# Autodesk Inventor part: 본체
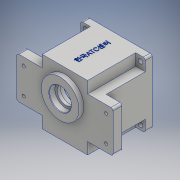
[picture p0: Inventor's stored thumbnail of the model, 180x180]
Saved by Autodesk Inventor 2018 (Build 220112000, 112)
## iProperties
Created: 2020-07
Part Number: 본체
Material: 알루미늄 6061
Document SubType Name: Modeling
Designer: admin
Density: 2.7 g/cm^3
Appearance: 알루미늄 - 평지
Mass: 876.486 g
Surface Area: 793.573 cm^2
Volume: 324.624 cm^3
Author: admin
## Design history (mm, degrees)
sketch "스케치1"
  geometry: L1 (65.8, 0)-(-65.8, 0) reference; L2 (0, -65.8)-(0, 65.8) reference; L3 (47, -47)-(-47, -47); L4 (-47, -47)-(-47, 47); L5 (-47, 47)-(47, 47); L6 (47, 47)-(47, -47); L7 (47, -47)-(-47, 47); L8 (-47, -47)-(47, 47); 1 further point
  constraints: 12 end point, 2 midpoint, 2 parallel, 1 horizontal, 1 perpendicular
  dimensions: "d0" = 94 distance of L4.end L5.end; "d1" = 94 distance of L3.end L4.end
extrude "돌출1" new body sketch "스케치1" stored distance "d2" = 67; taper "d3" = 0 deg
sketch "스케치2"
  geometry: L1 (47, -47)-(-47, -47) reference; L2 (-47, -47)-(-47, 47) reference; L3 (-47, 47)-(47, 47) reference; L4 (47, 47)-(47, -47) reference; L5 (-98, 0)-(98, 0) reference; L6 (0, -65.8)-(0, 65.8) reference; L7 (33, -47)-(-33, -47); L8 (-33, 47)-(33, 47); L9 (33, -47)-(-33, 47); L10 (-33, -47)-(33, 47); L11 (-70, -30)-(-70, 30); L12 (70, 30)-(70, -30); L13 (70, -30)-(-70, 30); L14 (-70, -30)-(70, 30); L15 (-70, 30)-(-33, 30); L16 (33, 30)-(70, 30); L17 (33, 47)-(33, 30); L18 (33, -30)-(33, -47); L19 (70, -30)-(33, -30); L20 (-33, -30)-(-70, -30); L21 (-33, -47)-(-33, -30); L22 (-33, 30)-(-33, 47); 1 further point
  constraints: 32 end point, 10 parallel, 4 midpoint, 4 perpendicular, 3 horizontal, 4 other
  dimensions: "d4" = 66 distance of L8.start L8.end; "d5" = 94 distance of L7.end L8.start; "d6" = 140 distance of L11.end L12.start; "d7" = 60 distance of L11.start L11.end
extrude "돌출3" join sketch "스케치2" distance "d10" = 13; taper "d11" = 0 deg
sketch "스케치5"
  geometry: L1 (-33, -47)-(33, -47) reference; L2 (33, -47)-(33, -30) reference; L3 (33, -30)-(70, -30) reference; L4 (70, -30)-(70, 30) reference; L5 (70, 30)-(33, 30) reference; L6 (33, 30)-(33, 47) reference; L7 (33, 47)-(-33, 47) reference; L8 (-33, 47)-(-33, 30) reference; L9 (-33, 30)-(-70, 30) reference; L10 (-70, 30)-(-70, -30) reference; L11 (-70, -30)-(-33, -30) reference; L12 (-33, -30)-(-33, -47) reference; L13 (-98, 0)-(98, 0) reference; L14 (0, -65.8)-(0, 65.8) reference; L15 (47, -47)-(-47, -47) reference; L16 (-47, -47)-(-47, 47) reference; L17 (-47, 47)-(47, 47) reference; L18 (47, 47)-(47, -47) reference; L19 (-47, 47)-(47, 47) reference; L20 (-47, 47)-(-33, 47); L21 (-33, 47)-(-33, 30); L22 (-33, 30)-(-47, 30); L23 (-47, 30)-(-47, 47); L24 (33, 47)-(47, 47); L25 (47, 47)-(47, 30); L26 (47, 30)-(33, 30); L27 (33, 30)-(33, 47); L28 (47, -47)-(-47, -47) reference; L29 (33, -30)-(47, -30); L30 (47, -30)-(47, -47); L31 (47, -47)-(33, -47); L32 (33, -47)-(33, -30); L33 (-47, -47)-(-47, 47) reference; L34 (-47, -30)-(-33, -30); L35 (-33, -30)-(-33, -47); L36 (-33, -47)-(-47, -47); L37 (-47, -47)-(-47, -30); 1 further point
  constraints: 32 end point, 8 parallel, 4 horizontal, 4 perpendicular, 4 point on line
extrude "돌출4" cut sketch "스케치5" distance "d12" = 57; taper "d13" = 0 deg
sketch "스케치6"
  geometry: L1 (47, 47)-(-47, 47) reference; L2 (-47, 47)-(-47, -47) reference; L3 (-47, -47)-(47, -47) reference; L4 (47, -47)-(47, 47) reference; L5 (-65.8, 0)-(65.8, 0) reference; L6 (0, 65.8)-(0, -65.8) reference; C1 r 40 at (0, 0); 1 further point
  constraints: 1 centre point, 1 coincident
  dimensions: "d14" = 80 diameter of C1
extrude "돌출5" cut sketch "스케치6" distance "d15" = 71; taper "d16" = 0 deg
sketch "스케치8"
  geometry: L1 (47, 47)-(-47, 47) reference; L2 (-47, 47)-(-47, -47) reference; L3 (-47, -47)-(47, -47) reference; L4 (47, -47)-(47, 47) reference; L5 (-98, 0)-(98, 0) reference; L6 (0, 65.8)-(0, -65.8) reference; C1 r 40 at (0, 0) reference; C2 r 21 at (0, -11); C3 r 15 at (0, 20); 1 further point
  constraints: 2 centre point, 2 point on line
  dimensions: "d22" = 42 diameter of C2; "d23" = 30 diameter of C3; "d24" = 11 distance from line of L5 C2.centre; "d25" = 20 distance of C3.centre point (0, 0)
extrude "돌출6" join sketch "스케치8" distance "d26" = 7; taper "d27" = 0 deg
sketch "스케치9"
  geometry: L1 (0, 65.8)-(0, -65.8) reference; L2 (-98, 0)-(98, 0) reference; C1 r 17.5 at (0, -11); A1 r 21 centre (0, -11) between (-8.978, 7.984) and (8.978, 7.984) reference; A2 r 15 centre (0, 20) between (8.978, 7.984) and (-8.978, 7.984) reference; 1 further point
  constraints: 1 centre point, 1 coincident
  dimensions: "d28" = 35 diameter of C1
extrude "돌출7" cut sketch "스케치9" distance "d29" = 10; taper "d30" = 0 deg
sketch "스케치10"
  geometry: L1 (-33, -47)-(33, -47) reference; L2 (33, -47)-(33, -30) reference; L3 (33, -30)-(70, -30) reference; L4 (70, -30)-(70, 30) reference; L5 (70, 30)-(33, 30) reference; L6 (33, 30)-(33, 47) reference; L7 (33, 47)-(-33, 47) reference; L8 (-33, 47)-(-33, 30) reference; L9 (-33, 30)-(-70, 30) reference; L10 (-70, 30)-(-70, -30) reference; L11 (-70, -30)-(-33, -30) reference; L12 (-33, -30)-(-33, -47) reference; L13 (-98, 0)-(98, 0) reference; L14 (0, -65.8)-(0, 65.8) reference; C1 r 17.5 at (0, 11) reference; C2 r 27.5 at (0, 11); A1 r 21 centre (0, 11) between (8.978, -7.984) and (-8.978, -7.984) reference; A2 r 15 centre (0, -20) between (-8.978, -7.984) and (8.978, -7.984) reference; 1 further point
  constraints: 1 centre point, 1 coincident
  dimensions: "d31" = 55 diameter of C2
extrude "돌출8" join sketch "스케치10" distance "d32" = 7; taper "d33" = 0 deg
sketch "스케치11"
  geometry: L1 (0, 76.8)-(0, -54.8) reference; L2 (-98, 11)-(98, 11) reference; C1 r 17.5 at (0, 0) reference; C2 r 40 at (0, 11) reference; C3 r 12.5 at (0, 0); A1 r 21 centre (0, 0) between (-8.978, 18.984) and (8.978, 18.984) reference; A2 r 15 centre (0, 31) between (8.978, 18.984) and (-8.978, 18.984) reference; A3 r 21 centre (0, 0) between (-8.978, 18.984) and (8.978, 18.984) reference; A4 r 15 centre (0, 31) between (8.978, 18.984) and (-8.978, 18.984) reference; 1 further point
  constraints: 1 centre point, 1 coincident
  dimensions: "d34" = 25 diameter of C3
extrude "돌출9" cut sketch "스케치11" extent not by distance; stored distance "d35" = 7; taper "d36" = 0 deg
sketch "스케치12"
  geometry: L1 (0, -76.8)-(0, 54.8) reference; L2 (-98, -11)-(98, -11) reference; C1 r 12.5 at (0, 0) reference; C2 r 27.5 at (0, 0) reference; C3 r 16 at (0, 0); 1 further point
  constraints: 1 centre point, 1 coincident
  dimensions: "d37" = 32 diameter of C3
extrude "돌출10" cut sketch "스케치12" distance "d38" = 8.3; taper "d39" = 0 deg
sketch "스케치13"
  geometry: L1 (47, 47)-(-47, 47) reference; L2 (-47, 47)-(-47, -47) reference; L3 (-47, -47)-(47, -47) reference; L4 (47, -47)-(47, 47) reference; L5 (-98, 0)-(98, 0) reference; L6 (0, 65.8)-(0, -65.8) reference; C1 r 17.5 at (0, -11) reference; C2 r 40 at (0, 0) reference; C3 r 11 at (0, 20); A1 r 21 centre (0, -11) between (-8.978, 7.984) and (8.978, 7.984) reference; A2 r 15 centre (0, 20) between (8.978, 7.984) and (-8.978, 7.984) reference; 1 further point
  constraints: 1 centre point, 1 coincident
  dimensions: "d40" = 22 diameter of C3
extrude "돌출11" cut sketch "스케치13" distance "d41" = 7; taper "d42" = 0 deg
sketch "스케치14"
  geometry: L1 (-98, -20)-(98, -20) reference; L2 (0, 45.8)-(0, -85.8) reference; C1 r 11 at (0, 0) reference; C2 r 11 at (0, 0) reference; C3 r 17.5 at (0, -31) reference; C4 r 9.5 at (0, 0); A1 r 21 centre (0, -31) between (-8.978, -12.016) and (8.978, -12.016) reference; A2 r 15 centre (0, 0) between (8.978, -12.016) and (-8.978, -12.016) reference; 1 further point
  constraints: 1 centre point, 1 coincident
  dimensions: "d43" = 19 diameter of C4
extrude "돌출12" cut sketch "스케치14" distance "d44" = 3; taper "d45" = 0 deg
sketch "스케치15"
  geometry: L1 (47, 47)-(-47, 47) reference; L2 (-47, 47)-(-47, -47) reference; L3 (-47, -47)-(47, -47) reference; L4 (47, -47)-(47, 47) reference; L5 (-98, 0)-(98, 0) reference; L6 (0, 65.8)-(0, -65.8) reference; C1 r 40 at (0, 0) reference; C2 r 43 at (0, 0); 1 further point
  constraints: 1 centre point, 1 coincident
  dimensions: "d46" = 86 diameter of C2
extrude "돌출13" cut sketch "스케치15" distance "d47" = 9; taper "d48" = 0 deg
sketch "스케치16" dims "d50" = 72
  geometry: L1 (47, 47)-(-47, 47) reference; L2 (-47, 47)-(-47, -47) reference; L3 (-47, -47)-(47, -47) reference; L4 (47, -47)-(47, 47) reference; L5 (-98, 0)-(98, 0) reference; L6 (0, 65.8)-(0, -65.8) reference; L7 (47, -4)-(36, -4); L8 (47, 4)-(36, 4); L9 (47, -4)-(47, 4); L10 (-47, -4)-(-36, -4); L11 (-47, 4)-(-36, 4); L12 (-47, -4)-(-47, 4); C1 r 43 at (0, 0) reference; A1 r 4 centre (36, 0) between (36, 4) and (36, -4); A2 r 4 centre (-36, 0) between (-36, -4) and (-36, 4); 2 further points
  constraints: 12 end point, 5 symmetric about line, 4 point on circle, 2 centre point, 2 collinear, 2 tangent, 1 coincident, 1 horizontal, 1 horizontal alignment, 1 parallel, 1 point on line, 1 vertical, 3 other
  dimensions: "d51" = 8 diameter of A1
extrude "돌출14" join sketch "스케치16" stored distance "d52" = 9; taper "d53" = 0 deg
sketch "스케치18"
  geometry: L1 (80, -10)-(94, -10) reference; L2 (94, 0)-(94, -10) reference; L3 (0, 0)-(94, 0) reference; L4 (0, 0)-(0, -10) reference; L5 (0, -10)-(14, -10) reference; L6 (14, -10)-(14, -80) reference; L7 (80, -80)-(14, -80) reference; L8 (80, -80)-(80, -10) reference; L9 (-51, -33.5)-(145, -33.5) reference; L10 (47, -104.4)-(47, 17.4) reference; 2 further points
  constraints: 1 point on line, 1 other
  dimensions: "d54" = 40 distance from line of L3 point (47, -40)
feature "엠보싱1" sketch "스케치18" dims "d0" = 94, "d1" = 94, "d55" = 0.5, "d56" = 0
sketch "스케치19"
  geometry: L1 (47, 30)-(47, -30) reference; L2 (47, -30)-(70, -30) reference; L3 (70, -30)-(70, 30) reference; L4 (70, 30)-(47, 30) reference; L5 (-47, -30)-(-47, 30) reference; L6 (-47, 30)-(-70, 30) reference; L7 (-70, 30)-(-70, -30) reference; L8 (-70, -30)-(-47, -30) reference; L9 (-98, 0)-(98, 0) reference; L10 (0, 65.9)-(0, -66.4) reference; L11 (-60, 19)-(60, 19); L12 (60, 19)-(60, -19); L13 (60, -19)-(-60, -19); L14 (-60, -19)-(-60, 19); L15 (-60, 19)-(60, -19); L16 (60, 19)-(-60, -19); C1 r 5 at (60, -19); C2 r 5 at (60, 19); C3 r 5 at (-60, -19); C4 r 5 at (-60, 19); 1 further point
  constraints: 12 end point, 4 centre point, 4 coincident, 2 midpoint, 2 parallel, 1 horizontal, 1 perpendicular
  dimensions: "d58" = 120 distance of L12.end L13.end; "d59" = 38 distance of L11.end L12.end; "d60" = 10 diameter of C1; "d61" = 10 diameter of C2; "d62" = 10 diameter of C3; "d63" = 10 diameter of C4
extrude "돌출15" cut sketch "스케치19" distance "d64" = 5; taper "d65" = 0 deg
sketch "스케치20"
  geometry: L1 (-13, 49)-(-13, -11) reference; L2 (-13, -11)-(10, -11) reference; L3 (10, -11)-(10, 49) reference; L4 (10, 49)-(-13, 49) reference; L5 (-107, -11)-(-107, 49) reference; L6 (-107, 49)-(-130, 49) reference; L7 (-130, 49)-(-130, -11) reference; L8 (-130, -11)-(-107, -11) reference; L9 (-158, 19)-(38, 19) reference; L10 (-60, 84.9)-(-60, -47.4) reference; C1 r 5 at (0, 0) reference; C2 r 5 at (0, 38) reference; C3 r 5 at (-120, 0) reference; C4 r 5 at (-120, 38) reference; C5 r 2.25 at (0, 0); C6 r 2.25 at (-120, 0); C7 r 2.25 at (0, 38); C8 r 2.25 at (-120, 38); 1 further point
  constraints: 4 centre point, 1 coincident, 1 horizontal, 1 vertical, 6 other
  dimensions: "d66" = 4.5 diameter of C5; "d69" = 120 distance of C5.centre C6.centre; "d72" = 38 distance of C5.centre C7.centre
extrude "돌출16" cut sketch "스케치20" stored distance "d75" = 5; taper "d76" = 0 deg
sketch "스케치21"
  geometry: L1 (36, 4)-(39.799, 4) reference; L2 (39.799, -4)-(36, -4) reference; L3 (-39.799, -4)-(-36, -4) reference; L4 (-36, 4)-(-39.799, 4) reference; C1 r 43 at (0, 0) reference; A1 r 4 centre (36, 0) between (36, 4) and (36, -4) reference; A2 r 40 centre (0, 0) between (-39.799, -4) and (39.799, -4) reference; A3 r 4 centre (-36, 0) between (-36, -4) and (-36, 4) reference; A4 r 40 centre (0, 0) between (39.799, 4) and (-39.799, 4) reference; 3 further points
  constraints: 2 coincident
hole "구멍1" sketch "스케치21" at (-36, 0), (36, 0) diameter "d77" = 3.242; stored, may be unused: countersink angle "d81" = 90 deg, drill point angle "d83" = 118 deg; dims "d78" = 7, "d79" = 4, "d80" = 2, "d82" = 9
sketch "스케치22"
  geometry: L1 (47, 47)-(-47, 47) reference; L2 (-47, 47)-(-47, -47) reference; L3 (-47, -47)-(47, -47) reference; L4 (47, -47)-(47, 47) reference; L5 (-98, 0)-(98, 0) reference; L6 (0, 65.9)-(0, -66.4) reference; L7 (-40, -40)-(40, -40); L8 (40, -40)-(40, 40); L9 (40, 40)-(-40, 40); L10 (-40, 40)-(-40, -40); L11 (-40, -40)-(40, 40); L12 (40, -40)-(-40, 40); C1 r 43 at (0, 0) reference; C2 r 3.5 at (-40, -40); C3 r 3.5 at (-40, 40); C4 r 3.5 at (40, 40); C5 r 3.5 at (40, -40); 1 further point
  constraints: 12 end point, 4 centre point, 4 coincident, 2 midpoint, 2 parallel, 1 horizontal, 1 perpendicular
  dimensions: "d84" = 80 distance of L9.end L8.end; "d85" = 80 distance of L8.end L7.end; "d86" = 7 diameter of C2; "d87" = 7 diameter of C3; "d88" = 7 diameter of C4; "d89" = 7 diameter of C5
extrude "돌출17" cut sketch "스케치22" stored distance "d90" = 5; taper "d91" = 0 deg
chamfer "모따기1" distance "d92" = 0.8; stored, may be unused: second distance "d93" = 2, angle "d94" = 30 deg
fillet "모깎기1" dims "d95" = 3
chamfer "모따기2" distance "d96" = 1; stored, may be unused: second distance "d97" = 2, angle "d98" = 30 deg
node "솔리드1"
node "투영된 루프1"
node "투영된 루프7"
node "투영된 루프8"
node "투영된 루프9"
node "투영된 루프12"
node "투영된 루프13"
node "투영된 루프14"
node "투영된 루프15"
node "투영된 루프16"
node "투영된 루프17"
node "투영된 루프18"
node "투영된 루프19"
node "투영된 루프20"
node "투영된 루프21"
node "투영된 루프22"
node "투영된 루프23"
node "투영된 루프24"
node "투영된 루프25"
node "투영된 루프26"
node "투영된 루프27"
node "투영된 루프28"
node "투영된 루프29"
node "투영된 루프30"
